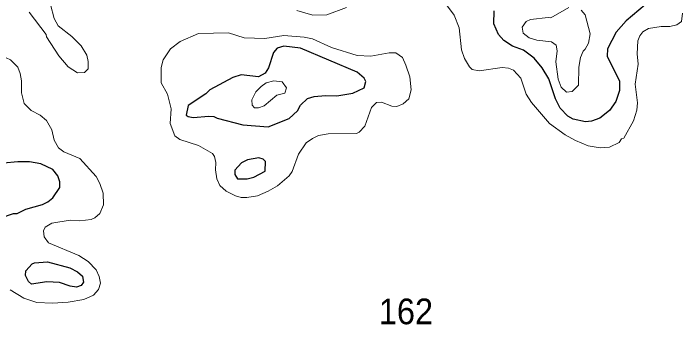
# Model space of a CAD drawing. Extents: x 763.2 to 816.8, y 7896.5 to 7952.7.
# Drawn here: x 810.254 to 814.429, y 7903.929 to 7905.868 of the extents above; entities that cross this region are included whole.
import ezdxf

# ---------------------------------------------------------------- set-up
doc = ezdxf.new("R2010")
doc.units = 0
doc.header["$LTSCALE"] = 0.064
doc.layers.add('1', color=7, linetype='Continuous', lineweight=25)
doc.layers.add('2', color=7, linetype='Continuous', lineweight=13)
doc.layers.add('21', color=7, linetype='Continuous')

msp = doc.modelspace()

# ---------------------------------------------------------------- linework, layer by layer
at = {"layer": '1'}
for points in [[(814.1959, 7905.9223), (814.076, 7905.8218), (814.0143, 7905.7504), (813.9609, 7905.6479), (813.9576, 7905.6007), (814.0361, 7905.4461), (814.0359, 7905.3869), (814.0114, 7905.3195), (813.9718, 7905.2628), (813.9128, 7905.2153), (813.8595, 7905.1969), (813.8225, 7905.1923), (813.7463, 7905.2086), (813.7133, 7905.2285), (813.6643, 7905.2782), (813.6359, 7905.335), (813.5952, 7905.4605), (813.5529, 7905.5289), (813.5032, 7905.5883), (813.4362, 7905.639), (813.3673, 7905.6639), (813.313, 7905.6999), (813.28, 7905.7368), (813.252, 7905.8034), (813.2527, 7905.8844)], [(810.175, 7904.5933), (810.2545, 7904.6199), (810.2765, 7904.621), (810.3317, 7904.647), (810.4346, 7904.6775), (810.4691, 7904.6938), (810.5005, 7904.7183), (810.5436, 7904.7836), (810.5436, 7904.819), (810.5317, 7904.8557), (810.5001, 7904.8949), (810.4254, 7904.9307), (810.3548, 7904.9436), (810.2816, 7904.9422), (810.1916, 7904.9346)]]:
    msp.add_lwpolyline(points, dxfattribs=at)
for points in [[(812.0894, 7905.3368), (812.1297, 7905.35), (812.2004, 7905.3564), (812.2727, 7905.3548), (812.372, 7905.3714), (812.4417, 7905.4046), (812.4525, 7905.4437), (812.4417, 7905.4647), (812.3991, 7905.501), (812.0452, 7905.6506), (811.9407, 7905.6636), (811.9002, 7905.6523), (811.8767, 7905.6241), (811.8454, 7905.5297), (811.8249, 7905.496), (811.7836, 7905.4727), (811.6755, 7905.4844), (811.6227, 7905.4683), (811.48, 7905.392), (811.4536, 7905.3675), (811.3443, 7905.2931), (811.3315, 7905.2339), (811.3437, 7905.2253), (811.3762, 7905.2184), (811.4733, 7905.2281), (811.5039, 7905.2252), (811.5255, 7905.2144), (811.6859, 7905.1743), (811.8442, 7905.1609), (811.9749, 7905.2128), (812.0256, 7905.2605), (812.0449, 7905.2962)], [(811.8265, 7904.9458), (811.8124, 7904.9601), (811.7857, 7904.9685), (811.7133, 7904.955), (811.6773, 7904.9368), (811.6352, 7904.8906), (811.6359, 7904.8636), (811.6524, 7904.8373), (811.7131, 7904.8371), (811.7532, 7904.8466), (811.8254, 7904.884)], [(810.3701, 7904.3064), (810.3852, 7904.3143), (810.4674, 7904.3192), (810.6062, 7904.2831), (810.6528, 7904.2581), (810.6843, 7904.2295), (810.6864, 7904.2165), (810.6904, 7904.1933), (810.676, 7904.1717), (810.6472, 7904.1627), (810.6078, 7904.1671), (810.5413, 7904.1909), (810.4624, 7904.1944), (810.367, 7904.1799), (810.3474, 7904.1961), (810.3287, 7904.2339), (810.3308, 7904.2641)]]:
    msp.add_lwpolyline(points, close=True, dxfattribs=at)
at = {"layer": '2'}
for points in [[(810.4845, 7905.9234), (810.5075, 7905.8353), (810.5338, 7905.7911), (810.6176, 7905.7243), (810.6768, 7905.6666), (810.7113, 7905.6078), (810.7212, 7905.5677), (810.7212, 7905.5219), (810.6981, 7905.4996), (810.6534, 7905.4974), (810.5947, 7905.534), (810.5374, 7905.6033), (810.4604, 7905.721), (810.458, 7905.7355), (810.3517, 7905.8753)], [(812.0222, 7905.8855), (812.1216, 7905.8561), (812.2093, 7905.8599), (812.3324, 7905.9041)], [(814.429, 7905.87), (814.4223, 7905.8173), (814.3934, 7905.7974), (814.3499, 7905.7863), (814.2942, 7905.7869), (814.2159, 7905.7739), (814.1815, 7905.7527), (814.1611, 7905.7277), (814.1493, 7905.6976), (814.1463, 7905.617), (814.1527, 7905.5526), (814.1331, 7905.4277), (814.1477, 7905.3114), (814.1427, 7905.2654), (814.1234, 7905.1977), (814.0614, 7905.0911), (814.0484, 7905.0858), (814.0322, 7905.0638), (813.973, 7905.0353), (813.9155, 7905.0295), (813.8395, 7905.0419), (813.7599, 7905.0754), (813.6955, 7905.1108), (813.5995, 7905.1817), (813.4852, 7905.3126), (813.4531, 7905.364), (813.4193, 7905.4637), (813.3738, 7905.5139), (813.3418, 7905.5274), (813.3032, 7905.5307), (813.1602, 7905.5109), (813.1166, 7905.5192), (813.0988, 7905.5359), (813.0676, 7905.5861), (813.0486, 7905.6401), (813.0351, 7905.7787), (813.0044, 7905.857), (812.9559, 7905.9215)], [(813.7186, 7905.9049), (813.6064, 7905.8398), (813.5901, 7905.8426), (813.4798, 7905.8299), (813.4523, 7905.8175), (813.4282, 7905.7813), (813.4334, 7905.744), (813.4714, 7905.7166), (813.5185, 7905.7017), (813.611, 7905.6899), (813.6394, 7905.6704), (813.6467, 7905.6352), (813.6384, 7905.5658), (813.6519, 7905.4588), (813.672, 7905.4088), (813.704, 7905.3777), (813.7406, 7905.3821), (813.7795, 7905.4197), (813.7815, 7905.5337), (813.7914, 7905.594), (813.8079, 7905.6322), (813.822, 7905.6452), (813.8425, 7905.6832), (813.852, 7905.7402), (813.8205, 7905.8591), (813.7951, 7905.8878)], [(809.814, 7905.886), (809.848, 7905.8155), (809.8765, 7905.7741), (809.9704, 7905.7141), (809.9749, 7905.7017), (810.0234, 7905.647), (810.0705, 7905.6227), (810.153, 7905.6157), (810.2352, 7905.5792), (810.2808, 7905.5327), (810.2963, 7905.494), (810.3053, 7905.4476), (810.304, 7905.3739), (810.3206, 7905.3072), (810.3651, 7905.2621), (810.4216, 7905.2335), (810.4602, 7905.2013), (810.4941, 7905.1417)], [(810.4941, 7905.1417), (810.5091, 7905.0781), (810.5344, 7905.0295), (810.5689, 7905.0061), (810.6692, 7904.9631), (810.7705, 7904.8518)], [(810.7705, 7904.8518), (810.794, 7904.8078), (810.8135, 7904.7476), (810.8166, 7904.6757), (810.7925, 7904.6208), (810.7613, 7904.5943), (810.7385, 7904.5842), (810.6687, 7904.5758), (810.6089, 7904.5789), (810.4926, 7904.5597), (810.4517, 7904.5356), (810.4419, 7904.513), (810.4457, 7904.4762), (810.4724, 7904.4384), (810.6627, 7904.3585), (810.7213, 7904.3226), (810.7711, 7904.2703), (810.7899, 7904.2287), (810.7967, 7904.1874), (810.7845, 7904.1472), (810.7529, 7904.1112), (810.6927, 7904.0854), (810.5964, 7904.068), (810.4978, 7904.0614), (810.3999, 7904.0662), (810.3197, 7904.0928), (810.2335, 7904.1451)]]:
    msp.add_lwpolyline(points, dxfattribs=at)
for points in [[(811.6943, 7905.7147), (811.8224, 7905.7114), (811.9407, 7905.7311), (812.0678, 7905.7208), (812.1201, 7905.7101), (812.2392, 7905.6558), (812.3991, 7905.606), (812.4837, 7905.6013), (812.5988, 7905.6227), (812.6393, 7905.6219), (812.6806, 7905.5937), (812.7032, 7905.5454), (812.7261, 7905.4731), (812.7361, 7905.391), (812.7215, 7905.3357), (812.6862, 7905.3036), (812.6461, 7905.2872), (812.6152, 7905.2889), (812.5494, 7905.315), (812.5187, 7905.313), (812.4879, 7905.2821), (812.4471, 7905.1648), (812.4117, 7905.1277), (812.3949, 7905.1187), (812.2168, 7905.1164), (812.1583, 7905.1066), (812.1196, 7905.0892), (812.0799, 7905.0617), (812.0328, 7904.9899), (811.9936, 7904.8826), (811.9744, 7904.8563), (811.9017, 7904.7932), (811.8442, 7904.7591), (811.7764, 7904.7319), (811.71, 7904.7204), (811.6754, 7904.7207), (811.639, 7904.73), (811.5812, 7904.76), (811.5412, 7904.7961), (811.523, 7904.8368), (811.5152, 7904.894), (811.5166, 7904.9389), (811.5084, 7904.9761), (811.4966, 7904.9946), (811.4082, 7905.0457), (811.2928, 7905.0817), (811.2602, 7905.1057), (811.2323, 7905.1812), (811.2373, 7905.2729), (811.2147, 7905.3651), (811.1754, 7905.4356), (811.1752, 7905.5312), (811.1878, 7905.5794), (811.2336, 7905.6468), (811.2938, 7905.6937), (811.4089, 7905.7426), (811.5952, 7905.7476)], [(811.7663, 7905.3796), (811.7989, 7905.4133), (811.8303, 7905.4348), (811.8789, 7905.4484), (811.9314, 7905.4406), (811.9569, 7905.4034), (811.9471, 7905.3715), (811.898, 7905.3579), (811.8185, 7905.292), (811.7822, 7905.2792), (811.7572, 7905.2793), (811.7438, 7905.2965), (811.7405, 7905.3291)]]:
    msp.add_lwpolyline(points, close=True, dxfattribs=at)

# ---------------------------------------------------------------- texts
at = {"layer": '21', "width": 0.95}
msp.add_text('162', height=0.16, dxfattribs=at).set_placement((812.5332, 7903.9308))

doc.saveas('drawing.dxf')
